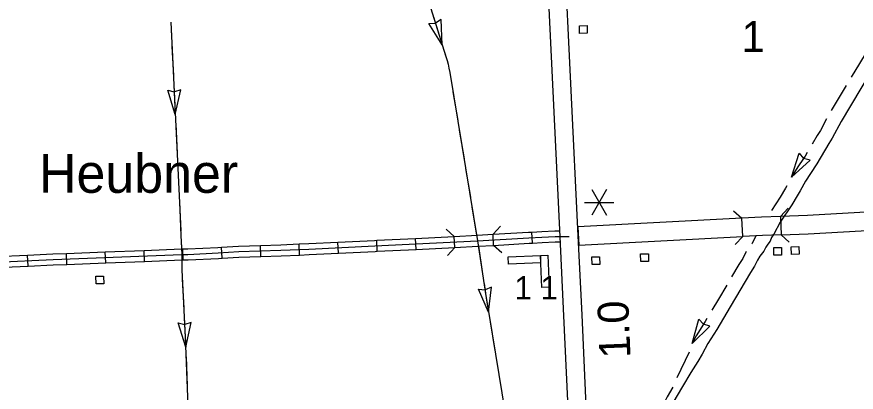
# Model space of a CAD drawing. Extents: x -0.3 to 2.65, y 0 to 1.9.
# Drawn here: x 0.7254 to 0.8619, y 0.3953 to 0.4564 of the extents above; entities that cross this region are included whole.
import ezdxf

# ---------------------------------------------------------------- set-up
doc = ezdxf.new("R2010")
doc.units = 0
for name, color, linetype in [('Level 12', 7, 'Continuous'), ('Level 15', 7, 'Continuous'), ('Level 16', 7, 'Continuous'), ('Level 19', 7, 'Continuous'), ('Level 20', 7, 'Continuous'), ('Level 21', 7, 'Continuous'), ('Level 25', 7, 'Continuous'), ('Level 29', 7, 'Continuous'), ('Level 30', 7, 'Continuous')]:
    doc.layers.add(name, color=color, linetype=linetype)

msp = doc.modelspace()

# ---------------------------------------------------------------- linework, layer by layer
at = {"layer": 'Level 12'}
for p, q in [((0.79239, 0.45531), (0.79348, 0.45536)), ((0.79458, 0.45184), (0.79239, 0.45531)), ((0.79442, 0.45594), (0.79349, 0.45536)), ((0.79458, 0.45184), (0.79442, 0.45594)), ((0.75115, 0.4405), (0.74992, 0.44442)), ((0.74992, 0.44442), (0.75099, 0.44419)), ((0.75205, 0.44451), (0.75101, 0.44417)), ((0.75115, 0.4405), (0.75205, 0.44451)), ((0.85143, 0.43027), (0.85266, 0.43419)), ((0.85143, 0.43027), (0.85445, 0.43305)), ((0.85266, 0.43419), (0.85339, 0.43329)), ((0.85445, 0.43305), (0.85339, 0.43329)), ((0.80213, 0.40829), (0.80049, 0.41205)), ((0.80049, 0.41205), (0.80157, 0.41193)), ((0.80259, 0.41237), (0.80159, 0.41193)), ((0.80213, 0.40829), (0.80259, 0.41237)), ((0.83523, 0.4032), (0.83635, 0.40718)), ((0.83635, 0.40718), (0.83709, 0.40637)), ((0.75161, 0.40655), (0.75268, 0.40632)), ((0.75284, 0.40263), (0.75161, 0.40655)), ((0.75374, 0.40664), (0.7527, 0.4063)), ((0.75284, 0.40263), (0.75374, 0.40664)), ((0.83523, 0.4032), (0.83814, 0.40603)), ((0.83814, 0.40603), (0.8371, 0.40636))]:
    msp.add_line(p, q, dxfattribs=at)
for points in [[(0.79106, 0.46314), (0.79518, 0.44993), (0.79538, 0.44924), (0.79554, 0.44865), (0.79566, 0.44801), (0.79581, 0.4473), (0.80033, 0.41993), (0.80169, 0.41097), (0.80222, 0.40776), (0.80533, 0.3889), (0.80862, 0.37283), (0.80865, 0.37236), (0.80883, 0.37157), (0.80906, 0.37094), (0.80998, 0.36655), (0.81009, 0.36589), (0.81015, 0.36502), (0.81051, 0.36349), (0.81075, 0.3628), (0.81108, 0.36244)], [(0.79317, 0.45636), (0.79458, 0.45184)], [(0.75042, 0.45549), (0.7519, 0.42495), (0.75207, 0.42077), (0.75219, 0.4177), (0.75219, 0.41519), (0.75278, 0.40422), (0.75329, 0.39033)], [(0.75042, 0.45549), (0.75054, 0.45312)], [(0.75061, 0.45154), (0.75084, 0.44681)], [(0.79505, 0.45033), (0.79518, 0.44993), (0.79538, 0.44924), (0.79554, 0.44865), (0.79565, 0.44804)], [(0.86359, 0.45059), (0.86246, 0.44879), (0.86112, 0.44655)], [(0.79565, 0.44804), (0.79566, 0.44801), (0.79581, 0.4473), (0.79607, 0.44571)], [(0.86436, 0.44751), (0.85947, 0.43935), (0.85803, 0.43663), (0.85748, 0.43576), (0.85552, 0.43244), (0.85448, 0.43086), (0.85369, 0.42964), (0.85281, 0.42804), (0.85234, 0.42723), (0.85146, 0.42576), (0.84959, 0.42293), (0.84852, 0.42102), (0.84817, 0.42047), (0.84793, 0.41986), (0.84759, 0.4194), (0.84725, 0.41888), (0.84693, 0.41822), (0.84628, 0.41742), (0.84588, 0.41678), (0.84537, 0.41577), (0.84473, 0.41477), (0.84144, 0.40916), (0.83925, 0.4055), (0.83778, 0.4032), (0.8369, 0.40148), (0.83616, 0.4003), (0.83503, 0.39848), (0.83366, 0.39622), (0.83211, 0.39357)], [(0.75092, 0.44523), (0.75115, 0.4405)], [(0.79633, 0.44415), (0.7971, 0.43948)], [(0.86031, 0.4452), (0.85787, 0.44113)], [(0.75122, 0.43892), (0.75145, 0.43419)], [(0.85711, 0.43975), (0.85613, 0.4379), (0.85558, 0.43704), (0.85476, 0.43564)], [(0.79736, 0.43792), (0.79813, 0.43324)], [(0.85395, 0.43428), (0.85362, 0.43372), (0.85268, 0.43228)], [(0.79839, 0.43169), (0.79916, 0.42701)], [(0.85268, 0.43228), (0.85258, 0.43213), (0.85179, 0.43092), (0.85143, 0.43027)], [(0.85066, 0.42889), (0.85044, 0.4285), (0.84956, 0.42703), (0.84814, 0.42488)], [(0.75183, 0.4263), (0.7519, 0.42495), (0.75203, 0.42157)], [(0.79942, 0.42545), (0.80018, 0.42082)], [(0.84563, 0.42074), (0.84503, 0.41949), (0.84498, 0.41943)], [(0.7521, 0.41999), (0.75215, 0.41859)], [(0.80046, 0.41904), (0.80115, 0.41453)], [(0.84405, 0.41816), (0.84399, 0.41806), (0.84347, 0.41705), (0.84283, 0.41604), (0.84167, 0.41406)], [(0.75219, 0.4168), (0.75219, 0.41525)], [(0.75227, 0.41367), (0.75252, 0.40894)], [(0.80138, 0.41297), (0.80169, 0.41097), (0.80174, 0.41063)], [(0.84087, 0.4127), (0.83954, 0.41044), (0.83846, 0.40862)], [(0.80174, 0.41063), (0.80213, 0.40829)], [(0.75261, 0.40736), (0.75278, 0.40422), (0.75284, 0.40263)], [(0.83765, 0.40727), (0.83736, 0.40678), (0.83588, 0.40447), (0.83523, 0.4032)], [(0.80239, 0.40673), (0.80316, 0.40206)], [(0.83475, 0.40182), (0.83274, 0.39761)], [(0.75289, 0.40105), (0.75307, 0.39632)], [(0.80342, 0.4005), (0.80419, 0.39582)], [(0.83212, 0.39612), (0.83119, 0.39453), (0.8306, 0.39333), (0.82965, 0.39156)]]:
    msp.add_lwpolyline(points, dxfattribs=at)
at = {"layer": 'Level 15'}
for p, q in [((0.80295, 0.41918), (0.80285, 0.42098)), ((0.80926, 0.41955), (0.80915, 0.42134)), ((0.77138, 0.41761), (0.77131, 0.41941)), ((0.7777, 0.4179), (0.77761, 0.4197)), ((0.78401, 0.41821), (0.78392, 0.42)), ((0.79032, 0.41853), (0.79023, 0.42032)), ((0.79663, 0.41885), (0.79654, 0.42064)), ((0.73982, 0.41632), (0.73975, 0.41811)), ((0.74613, 0.41656), (0.74606, 0.41836)), ((0.75243, 0.4168), (0.75239, 0.4186)), ((0.75878, 0.41708), (0.75866, 0.41887)), ((0.76506, 0.41738), (0.765, 0.41917)), ((0.7272, 0.41581), (0.72712, 0.4176)), ((0.7335, 0.41608), (0.73344, 0.41787))]:
    msp.add_line(p, q, dxfattribs=at)
for points in [[(0.79654, 0.42064), (0.80028, 0.42083), (0.80285, 0.42098)], [(0.80285, 0.42098), (0.80862, 0.42131), (0.80915, 0.42134)], [(0.80915, 0.42134), (0.81077, 0.42143), (0.81293, 0.42152), (0.81369, 0.42153)], [(0.68929, 0.41489), (0.71362, 0.41615), (0.71782, 0.41631), (0.72066, 0.41639), (0.72192, 0.41647), (0.73125, 0.41689), (0.75219, 0.4177), (0.75321, 0.41772), (0.75812, 0.41794), (0.76147, 0.41816), (0.76833, 0.41839), (0.77289, 0.41857), (0.78363, 0.41909), (0.80033, 0.41993), (0.80867, 0.42041), (0.81081, 0.42054), (0.81295, 0.42062), (0.81523, 0.42064)], [(0.765, 0.41917), (0.7683, 0.41929), (0.77131, 0.41941)], [(0.77131, 0.41941), (0.77285, 0.41947), (0.77761, 0.4197)], [(0.77761, 0.4197), (0.78358, 0.41999), (0.78392, 0.42)], [(0.78392, 0.42), (0.79023, 0.42032)], [(0.79023, 0.42032), (0.79654, 0.42064)], [(0.80295, 0.41918), (0.80873, 0.41952), (0.80926, 0.41955)], [(0.80926, 0.41955), (0.81086, 0.41964), (0.81297, 0.41973), (0.81377, 0.41973)], [(0.73344, 0.41787), (0.73975, 0.41811)], [(0.73975, 0.41811), (0.74606, 0.41836)], [(0.74606, 0.41836), (0.75216, 0.41859), (0.75239, 0.4186)], [(0.75239, 0.4186), (0.75319, 0.41861), (0.75807, 0.41883), (0.75866, 0.41887)], [(0.75866, 0.41887), (0.76142, 0.41905), (0.765, 0.41917)], [(0.7777, 0.4179), (0.78367, 0.41819), (0.78401, 0.41821)], [(0.78401, 0.41821), (0.79032, 0.41853)], [(0.79032, 0.41853), (0.79663, 0.41885)], [(0.79663, 0.41885), (0.80038, 0.41904), (0.80295, 0.41918)], [(0.72152, 0.41734), (0.72187, 0.41737), (0.72712, 0.4176)], [(0.72712, 0.4176), (0.73121, 0.41778), (0.73344, 0.41787)], [(0.74613, 0.41656), (0.75221, 0.4168), (0.75243, 0.4168)], [(0.75243, 0.4168), (0.75324, 0.41682), (0.75817, 0.41704), (0.75878, 0.41708)], [(0.75878, 0.41708), (0.76151, 0.41726), (0.76506, 0.41738)], [(0.76506, 0.41738), (0.76836, 0.41749), (0.77138, 0.41761)], [(0.77138, 0.41761), (0.77293, 0.41767), (0.7777, 0.4179)], [(0.7216, 0.41555), (0.72197, 0.41557), (0.7272, 0.41581)], [(0.7272, 0.41581), (0.73129, 0.41599), (0.7335, 0.41608)], [(0.7335, 0.41608), (0.73982, 0.41632)], [(0.73982, 0.41632), (0.74613, 0.41656)]]:
    msp.add_lwpolyline(points, dxfattribs=at)
at = {"layer": 'Level 16'}
for p, q in [((0.82131, 0.42825), (0.81892, 0.42411)), ((0.81892, 0.42825), (0.82131, 0.42411)), ((0.81772, 0.42618), (0.82251, 0.42618))]:
    msp.add_line(p, q, dxfattribs=at)
at = {"layer": 'Level 19'}
for points in [[(0.81815, 0.45494), (0.81818, 0.45369), (0.81693, 0.45366), (0.8169, 0.4549)], [(0.84979, 0.41882), (0.84981, 0.41758), (0.84856, 0.41756), (0.84854, 0.41881)], [(0.85262, 0.41899), (0.85267, 0.41774), (0.85143, 0.41769), (0.85138, 0.41894)], [(0.80537, 0.41614), (0.80532, 0.41733), (0.81055, 0.41755), (0.8106, 0.41636)], [(0.81055, 0.41755), (0.81175, 0.41761), (0.81199, 0.41238), (0.81079, 0.41232)], [(0.8202, 0.41733), (0.82024, 0.41609), (0.81899, 0.41605), (0.81895, 0.41729)], [(0.82812, 0.41782), (0.82813, 0.41658), (0.82688, 0.41657), (0.82687, 0.41781)], [(0.73949, 0.41417), (0.7395, 0.41292), (0.73825, 0.41291), (0.73824, 0.41416)]]:
    msp.add_lwpolyline(points, close=True, dxfattribs=at)
at = {"layer": 'Level 21'}
for points in [[(0.81443, 0.4681), (0.81144, 0.46796), (0.81373, 0.42057), (0.81434, 0.40771), (0.81519, 0.38928), (0.81551, 0.37423), (0.81555, 0.37264), (0.81855, 0.37272)], [(0.81855, 0.37272), (0.8185, 0.3743), (0.81818, 0.38938), (0.81733, 0.40785), (0.81672, 0.42071), (0.81443, 0.4681)], [(0.89038, 0.42493), (0.89004, 0.4279), (0.88912, 0.4278), (0.88703, 0.42747), (0.88456, 0.42711), (0.88227, 0.42674), (0.88067, 0.42654), (0.87808, 0.42623), (0.87639, 0.42595), (0.8751, 0.42576), (0.87152, 0.42526), (0.87022, 0.42514), (0.86894, 0.42498), (0.8679, 0.42489), (0.86634, 0.42473), (0.86466, 0.42465), (0.86256, 0.42453), (0.85402, 0.42405), (0.84965, 0.4239)], [(0.84965, 0.4239), (0.84975, 0.42091), (0.85415, 0.42106), (0.86273, 0.42154), (0.86482, 0.42166), (0.86656, 0.42175), (0.86818, 0.42191), (0.86925, 0.422), (0.87054, 0.42216), (0.87186, 0.42228), (0.87552, 0.4228), (0.87685, 0.42299), (0.87851, 0.42327), (0.88102, 0.42357), (0.88269, 0.42377), (0.88502, 0.42415), (0.88748, 0.42452), (0.88951, 0.42483), (0.89038, 0.42493)], [(0.84347, 0.42063), (0.84331, 0.42362), (0.81665, 0.42221), (0.81679, 0.41923)], [(0.84965, 0.4239), (0.84656, 0.42379), (0.84331, 0.42362)], [(0.84975, 0.42091), (0.84669, 0.4208), (0.84347, 0.42063)], [(0.81679, 0.41923), (0.84347, 0.42063)]]:
    msp.add_lwpolyline(points, dxfattribs=at)
at = {"layer": 'Level 29'}
for points in [[(0.80285, 0.42098), (0.80404, 0.42232)], [(0.79521, 0.42184), (0.79654, 0.42064)], [(0.79663, 0.41885), (0.79543, 0.41752)], [(0.80429, 0.41799), (0.80295, 0.41918)]]:
    msp.add_lwpolyline(points, dxfattribs=at)
at = {"layer": 'Level 30'}
for points in [[(0.84198, 0.42482), (0.84331, 0.42362)], [(0.84965, 0.4239), (0.85087, 0.42521)], [(0.85106, 0.41968), (0.84975, 0.42091)], [(0.84347, 0.42063), (0.84227, 0.4193)]]:
    msp.add_lwpolyline(points, dxfattribs=at)

# ---------------------------------------------------------------- texts
at = {"layer": 'Level 16'}
msp.add_text('1.0', height=0.00505, rotation=92.2845, dxfattribs=at).set_placement((0.82523, 0.40091))
at = {"layer": 'Level 19'}
msp.add_text('1 1', height=0.003791, dxfattribs=at).set_placement((0.80634, 0.41038))
at = {"layer": 'Level 20'}
msp.add_text('1', height=0.00505, dxfattribs=at).set_placement((0.84329, 0.45063))
at = {"layer": 'Level 25'}
msp.add_text('Heubner', height=0.006318, dxfattribs=at).set_placement((0.72897, 0.42773))

doc.saveas('drawing.dxf')
